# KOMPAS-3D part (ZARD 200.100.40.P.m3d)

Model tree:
1. Поверхность без истории:1
2. Поверхность без истории:2
3. Поверхность без истории:3
4. Поверхность без истории:4
5. Поверхность без истории:5
6. Поверхность без истории:6
7. Поверхность без истории:7
8. Поверхность без истории:8
9. Поверхность без истории:9
10. Поверхность без истории:10
11. Поверхность без истории:11
12. Поверхность без истории:12
13. Поверхность без истории:13
14. Поверхность без истории:14
15. Поверхность без истории:15
16. Поверхность без истории:16
17. Поверхность без истории:17
18. Поверхность без истории:18
19. Поверхность без истории:19
20. Поверхность без истории:20
21. Поверхность без истории:21
22. Поверхность без истории:22
23. Поверхность без истории:23
24. Поверхность без истории:24
25. Поверхность без истории:25
26. Поверхность без истории:26
27. Поверхность без истории:27
28. Поверхность без истории:28
29. Поверхность без истории:29
30. Поверхность без истории:30
31. Поверхность без истории:31
32. Поверхность без истории:32
33. Поверхность без истории:33
34. Поверхность без истории:34
35. Поверхность без истории:35
36. Поверхность без истории:36
37. Поверхность без истории:37
38. Поверхность без истории:38
39. Поверхность без истории:39
40. Поверхность без истории:40
41. Поверхность без истории:41
42. Поверхность без истории:42
43. Поверхность без истории:43
44. Поверхность без истории:44
45. Поверхность без истории:45
46. Поверхность без истории:46
47. Поверхность без истории:47
48. Поверхность без истории:48
49. Поверхность без истории:49
50. Поверхность без истории:50
51. Поверхность без истории:51
52. Поверхность без истории:52
53. Поверхность без истории:53
54. Поверхность без истории:54
55. Поверхность без истории:55
56. Поверхность без истории:56
57. Поверхность без истории:57
58. Поверхность без истории:58
59. Поверхность без истории:59
60. Поверхность без истории:60
61. Поверхность без истории:61
62. Поверхность без истории:62
63. Поверхность без истории:63
64. Поверхность без истории:64
65. Поверхность без истории:65
66. Поверхность без истории:66
67. Поверхность без истории:67
68. Поверхность без истории:68
69. Поверхность без истории:69
70. Поверхность без истории:70
71. Поверхность без истории:71
72. Поверхность без истории:72
73. Поверхность без истории:73
74. Поверхность без истории:74
75. Поверхность без истории:75
76. Поверхность без истории:76
77. Поверхность без истории:77
78. Поверхность без истории:78
79. Поверхность без истории:79
80. Поверхность без истории:80
81. Поверхность без истории:81
82. Поверхность без истории:82
83. Поверхность без истории:83
84. Поверхность без истории:84
85. Поверхность без истории:85
86. Поверхность без истории:86
87. Поверхность без истории:87
88. Поверхность без истории:88
89. Поверхность без истории:89
90. Поверхность без истории:90
91. Поверхность без истории:91
92. Поверхность без истории:92
93. Поверхность без истории:93
94. Поверхность без истории:94
95. Поверхность без истории:95
96. Поверхность без истории:96
97. Поверхность без истории:97
98. Поверхность без истории:98
99. Поверхность без истории:99
100. Поверхность без истории:100
101. Поверхность без истории:101
102. Поверхность без истории:102
103. Поверхность без истории:103
104. Поверхность без истории:104
105. Поверхность без истории:105

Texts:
  ЗАРД 200.100.40-ХХ.Р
